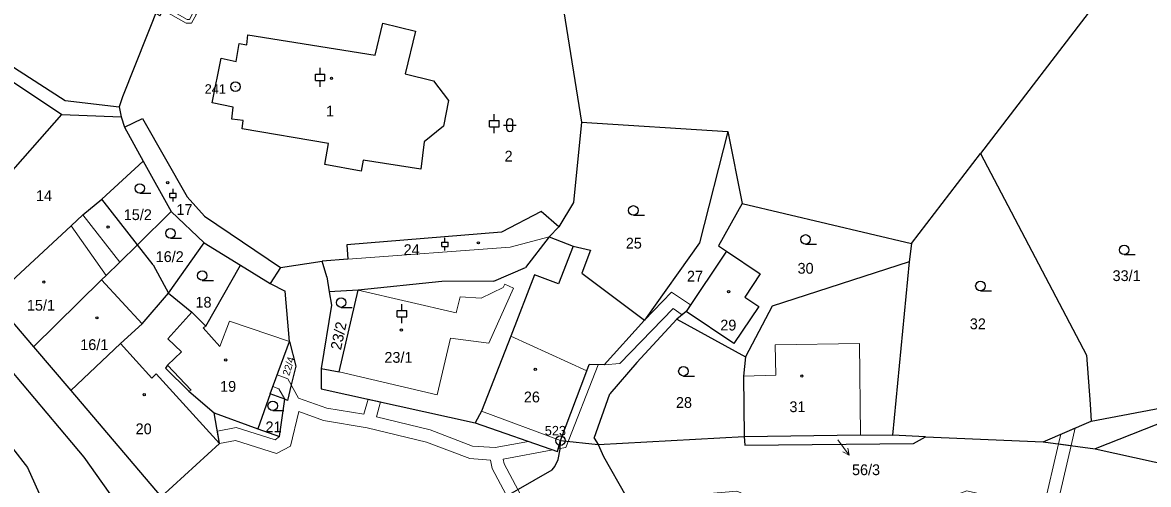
# Model space of a CAD drawing. Extents: x -727701 to -724405, y -960481 to -957284.
# Drawn here: x -726807.6 to -726630.1, y -958094.8 to -958022 of the extents above; entities that cross this region are included whole.
import ezdxf
from ezdxf.enums import TextEntityAlignment as Align

# ---------------------------------------------------------------- set-up
doc = ezdxf.new("R2010")
doc.units = 0
doc.header["$LTSCALE"] = 0.68
for name, color, linetype, lineweight in [('1', 7, 'Continuous', 25), ('13', 7, 'Continuous', 13), ('3', 7, 'Continuous', 25), ('4', 7, 'Continuous', 13), ('5', 7, 'Continuous', 25), ('7', 7, 'Continuous', 13), ('8', 7, 'Continuous', 25)]:
    doc.layers.add(name, color=color, linetype=linetype, lineweight=lineweight)
doc.layers.add('2', color=7, linetype='Continuous')

msp = doc.modelspace()

# ---------------------------------------------------------------- linework, layer by layer
at = {"layer": '1'}
for p, q in [((-726634.18, -958013.37), (-726656.63, -958042.62)), ((-726786, -958019), (-726791.84, -958033.67)), ((-726722.3, -958020.3), (-726719.49, -958037.65)), ((-726752.03, -958027.13), (-726750.81, -958022.07)), ((-726750.81, -958022.07), (-726745.67, -958023.32)), ((-726772.22, -958025.48), (-726772.11, -958023.89)), ((-726772.11, -958023.89), (-726752.03, -958027.13)), ((-726745.67, -958023.32), (-726747.3, -958030.05)), ((-726773.92, -958028.08), (-726773.45, -958025.28)), ((-726773.45, -958025.28), (-726772.22, -958025.48)), ((-726777.71, -958034.63), (-726776.28, -958027.6)), ((-726776.28, -958027.6), (-726773.92, -958028.08)), ((-726813.67, -958028.25), (-726801.41, -958036.44)), ((-726809.73, -958028.54), (-726800.87, -958034.27)), ((-726747.3, -958030.05), (-726742.82, -958031.14)), ((-726742.82, -958031.14), (-726740.46, -958034.25)), ((-726800.87, -958034.27), (-726792.34, -958035.24)), ((-726791.84, -958033.67), (-726792.34, -958035.24)), ((-726792.34, -958035.24), (-726792.05, -958036.83)), ((-726774.42, -958035.3), (-726777.71, -958034.63)), ((-726774.61, -958037.2), (-726774.42, -958035.3)), ((-726740.46, -958034.25), (-726741.23, -958038.3)), ((-726811, -958047.4), (-726801.41, -958036.44)), ((-726801.41, -958036.44), (-726792.05, -958036.83)), ((-726792.05, -958036.83), (-726791.53, -958038.45)), ((-726791.53, -958038.45), (-726788.71, -958037.06)), ((-726788.71, -958037.06), (-726781.66, -958049.45)), ((-726791.53, -958038.45), (-726788.56, -958043.82)), ((-726772.84, -958037.39), (-726774.61, -958037.2)), ((-726772.98, -958038.69), (-726772.84, -958037.39)), ((-726759.37, -958041.03), (-726772.98, -958038.69)), ((-726741.23, -958038.3), (-726744.3, -958040.75)), ((-726719.49, -958037.65), (-726720.78, -958050.32)), ((-726719.49, -958037.65), (-726696.44, -958039.15)), ((-726696.44, -958039.15), (-726700.89, -958056.67)), ((-726696.44, -958039.15), (-726694.19, -958050.5)), ((-726759.97, -958044.33), (-726759.37, -958041.03)), ((-726744.3, -958040.75), (-726744.8, -958045.05)), ((-726795.1, -958049.78), (-726788.56, -958043.82)), ((-726788.56, -958043.82), (-726784.19, -958051.72)), ((-726753.89, -958043.63), (-726754.21, -958045.38)), ((-726744.8, -958045.05), (-726753.89, -958043.63)), ((-726667.48, -958056.8), (-726656.63, -958042.62)), ((-726656.63, -958042.62), (-726639.88, -958074.4)), ((-726754.21, -958045.38), (-726759.97, -958044.33)), ((-726781.66, -958049.45), (-726778.93, -958052.5)), ((-726798.08, -958052.29), (-726795.1, -958049.78)), ((-726789.5, -958056.98), (-726795.1, -958049.78)), ((-726720.78, -958050.32), (-726723.08, -958054.16)), ((-726694.19, -958050.5), (-726697.9, -958057.17)), ((-726694.19, -958050.5), (-726667.48, -958056.8)), ((-726799.94, -958054), (-726798.08, -958052.29)), ((-726784.19, -958051.72), (-726778.95, -958056.7)), ((-726778.93, -958052.5), (-726766.93, -958060.55)), ((-726725.86, -958051.74), (-726732.1, -958055)), ((-726723.08, -958054.16), (-726725.86, -958051.74)), ((-726812.34, -958065.48), (-726799.94, -958054)), ((-726723.08, -958054.16), (-726724.57, -958055.73)), ((-726826.51, -958056.58), (-726797.94, -958090.46)), ((-726732.1, -958055), (-726756.5, -958057)), ((-726724.57, -958055.73), (-726728.3, -958060.55)), ((-726724.57, -958055.73), (-726720.82, -958057.18)), ((-726787.03, -958060.16), (-726789.5, -958056.98)), ((-726784.57, -958064.63), (-726778.95, -958056.7)), ((-726778.95, -958056.7), (-726773.25, -958060.2)), ((-726756.5, -958057), (-726756.3, -958059.27)), ((-726720.82, -958057.18), (-726723.14, -958063.16)), ((-726720.82, -958057.18), (-726718.08, -958057.84)), ((-726718.08, -958057.84), (-726719.46, -958061.48)), ((-726700.89, -958056.67), (-726709.57, -958068.85)), ((-726696.65, -958058), (-726703, -958067.5)), ((-726697.9, -958057.17), (-726696.65, -958058)), ((-726696.65, -958058), (-726691.31, -958061.57)), ((-726667.48, -958056.8), (-726667.86, -958059.69)), ((-726794.39, -958061.81), (-726792.27, -958059.72)), ((-726766.93, -958060.55), (-726760.36, -958059.59)), ((-726756.3, -958059.27), (-726760.36, -958059.59)), ((-726759.65, -958062.02), (-726760.36, -958059.59)), ((-726667.86, -958059.69), (-726689.43, -958066.67)), ((-726667.86, -958059.69), (-726670.46, -958087.01)), ((-726795.13, -958062.49), (-726794.39, -958061.81)), ((-726787.03, -958060.16), (-726784.57, -958064.63)), ((-726778.7, -958069.8), (-726773.25, -958060.2)), ((-726773.25, -958060.2), (-726768.55, -958063.1)), ((-726766.93, -958060.55), (-726768.55, -958063.1)), ((-726733.3, -958062.7), (-726728.3, -958060.55)), ((-726726.89, -958061.7), (-726730.65, -958071.41)), ((-726723.14, -958063.16), (-726726.89, -958061.7)), ((-726719.46, -958061.48), (-726709.57, -958068.85)), ((-726691.31, -958061.57), (-726693.76, -958065.26)), ((-726805.89, -958073.05), (-726795.13, -958062.49)), ((-726768.55, -958063.1), (-726766.22, -958064.32)), ((-726759.65, -958062.02), (-726759.24, -958064.42)), ((-726741.5, -958062.75), (-726754.68, -958064.12)), ((-726733.3, -958062.7), (-726741.5, -958062.75)), ((-726788.76, -958069.46), (-726784.57, -958064.63)), ((-726784.57, -958064.63), (-726780.9, -958067.59)), ((-726765.53, -958072.25), (-726766.22, -958064.32)), ((-726754.68, -958064.12), (-726759.24, -958064.42)), ((-726759.24, -958064.42), (-726758.89, -958066.48)), ((-726757.7, -958077.03), (-726754.68, -958064.12)), ((-726693.76, -958065.26), (-726691.57, -958066.7)), ((-726812.34, -958065.48), (-726805.89, -958073.05)), ((-726758.89, -958066.48), (-726760.54, -958076.51)), ((-726691.57, -958066.7), (-726695.47, -958072.54)), ((-726689.43, -958066.67), (-726693.66, -958074.62)), ((-726780.9, -958067.59), (-726784.71, -958071.83)), ((-726780.9, -958067.59), (-726778.7, -958069.8)), ((-726709.57, -958068.85), (-726715.94, -958075.93)), ((-726704.45, -958068.71), (-726710.79, -958075.52)), ((-726703, -958067.5), (-726704.45, -958068.71)), ((-726704.45, -958068.71), (-726693.66, -958074.62)), ((-726695.47, -958072.54), (-726703, -958067.5)), ((-726792.14, -958072.55), (-726788.76, -958069.46)), ((-726799.99, -958079.97), (-726792.14, -958072.55)), ((-726784.71, -958071.83), (-726782.55, -958073.85)), ((-726768.55, -958080.5), (-726765.53, -958072.25)), ((-726765.53, -958072.25), (-726764.5, -958076.13)), ((-726730.65, -958071.41), (-726735.23, -958083.21)), ((-726805.89, -958073.05), (-726799.99, -958079.97)), ((-726782.55, -958073.85), (-726784.75, -958075.94)), ((-726784.75, -958075.94), (-726785.05, -958076.45)), ((-726718.68, -958076.86), (-726718.3, -958075.85)), ((-726715.94, -958075.93), (-726718.3, -958075.85)), ((-726710.79, -958075.52), (-726715.02, -958080.5)), ((-726693.66, -958074.62), (-726693.94, -958077.71)), ((-726639.88, -958074.4), (-726639.34, -958082.13)), ((-726785.05, -958076.45), (-726781.41, -958080.08)), ((-726760.54, -958076.51), (-726760.53, -958079.68)), ((-726760.54, -958076.51), (-726757.7, -958077.03)), ((-726722.81, -958087.85), (-726718.68, -958076.86)), ((-726693.94, -958077.71), (-726693.86, -958087.19)), ((-726639.17, -958084.77), (-726610.68, -958079.34)), ((-726799.99, -958079.97), (-726785.73, -958096.72)), ((-726781.41, -958080.08), (-726777.38, -958083.49)), ((-726768.55, -958080.5), (-726770.5, -958086)), ((-726766.26, -958081.33), (-726768.55, -958080.5)), ((-726767.08, -958087.21), (-726766.26, -958081.33)), ((-726760.53, -958079.68), (-726736.26, -958085.03)), ((-726717.51, -958087.44), (-726715.02, -958080.5)), ((-726735.23, -958083.21), (-726736.26, -958085.03)), ((-726639.34, -958082.13), (-726639.17, -958084.77)), ((-726813.46, -958083.54), (-726806.79, -958092.11)), ((-726776.53, -958088.3), (-726777.38, -958083.49)), ((-726777.38, -958083.49), (-726770.5, -958086)), ((-726646.73, -958088.04), (-726639.17, -958084.77)), ((-726627.07, -958084.61), (-726638.52, -958089.14)), ((-726770.5, -958086), (-726767.08, -958087.21)), ((-726736.26, -958085.03), (-726723.27, -958089.58)), ((-726785.73, -958096.72), (-726776.53, -958088.3)), ((-726723.27, -958089.58), (-726722.81, -958087.85)), ((-726722.87, -958089.2), (-726722.81, -958087.85)), ((-726722.81, -958087.85), (-726716.86, -958088.47)), ((-726717.51, -958087.44), (-726716.86, -958088.47)), ((-726716.86, -958088.47), (-726693.86, -958087.19)), ((-726716.86, -958088.47), (-726716.02, -958090.34)), ((-726693.86, -958087.19), (-726675.5, -958086.94)), ((-726693.86, -958087.19), (-726693.74, -958088.58)), ((-726693.74, -958088.58), (-726667.19, -958088.31)), ((-726675.5, -958086.94), (-726670.46, -958087.01)), ((-726665.3, -958087.23), (-726670.46, -958087.01)), ((-726667.19, -958088.31), (-726665.3, -958087.23)), ((-726665.3, -958087.23), (-726646.73, -958088.04)), ((-726646.73, -958088.04), (-726638.52, -958089.14)), ((-726723.18, -958090.81), (-726722.87, -958089.2)), ((-726638.52, -958089.14), (-726614.35, -958094.5)), ((-726797.94, -958090.46), (-726791.6, -958099.4)), ((-726724.12, -958092.43), (-726723.68, -958091.94)), ((-726723.68, -958091.94), (-726723.18, -958090.81)), ((-726716.02, -958090.34), (-726712.52, -958096.53)), ((-726806.79, -958092.11), (-726802.49, -958101.65)), ((-726762.74, -958114.62), (-726724.12, -958092.43))]:
    msp.add_line(p, q, dxfattribs=at)
for points in [[(-726792.27, -958059.72), (-726789.5, -958056.98), (-726784.19, -958051.72)], [(-726764.5, -958076.13), (-726765.26, -958079.07), (-726765.82, -958081.51), (-726766.26, -958081.33)]]:
    msp.add_lwpolyline(points, dxfattribs=at)
at = {"layer": '13'}
for points in [[(-726785.68, -958019.12), (-726786.46, -958020.56), (-726785.95, -958020.93), (-726785.44, -958020.01), (-726781.83, -958022.08), (-726780.94, -958022.08), (-726780.17, -958020.62), (-726780.77, -958020.46), (-726781.3, -958021.48), (-726781.67, -958021.48), (-726785.15, -958019.49), (-726785.07, -958019.34)], [(-726705.3, -958064.45), (-726709.57, -958068.85), (-726715.94, -958075.93), (-726713.47, -958075.71), (-726705.03, -958067.04), (-726703.61, -958068.01), (-726703, -958067.5), (-726702.31, -958066.47)], [(-726718.3, -958075.85), (-726718.68, -958076.86), (-726722.81, -958087.85), (-726723.16, -958089.16), (-726721.98, -958088.95), (-726716.85, -958075.9)], [(-726643.94, -958086.83), (-726644.3, -958088.37), (-726642.31, -958088.63), (-726641.66, -958085.85)]]:
    msp.add_lwpolyline(points, close=True, dxfattribs=at)
for points in [[(-726725.49, -958103.19), (-726731.67, -958091.53), (-726731.84, -958090.75), (-726724.02, -958089.32), (-726727.83, -958087.98), (-726733.1, -958088.95), (-726736.65, -958088.72), (-726743.33, -958086.16), (-726751.82, -958084.1), (-726751.18, -958081.74), (-726753.13, -958081.31), (-726753.79, -958083.69), (-726759.64, -958082.72), (-726764.08, -958081.15), (-726765.78, -958078.1), (-726767.44, -958077.46), (-726768.13, -958079.34), (-726767.18, -958079.71), (-726766.26, -958081.33), (-726767.08, -958087.21), (-726767.76, -958087.72), (-726773.92, -958085.76), (-726776.88, -958086.34), (-726776.53, -958088.3), (-726774.03, -958087.82), (-726767.59, -958089.88), (-726765.38, -958088.75), (-726764.06, -958083.28), (-726760.14, -958084.66), (-726753.26, -958085.81), (-726743.92, -958088.07), (-726737.08, -958090.69), (-726733.86, -958090.91), (-726733.57, -958092.23), (-726727.05, -958104.51)], [(-726604.4, -958109.65), (-726644.73, -958099.04), (-726642.31, -958088.63), (-726644.3, -958088.37), (-726646.67, -958098.54), (-726658.74, -958095.77), (-726661.5, -958096.77), (-726693.5, -958096.46), (-726694.99, -958095.83), (-726709.76, -958097.1), (-726711.37, -958097.43), (-726710.03, -958098.34), (-726693, -958097.2), (-726661.42, -958098.23), (-726660, -958098.35), (-726658.6, -958097.84), (-726652.45, -958099.16), (-726652.59, -958099.8), (-726650.64, -958100.26), (-726650.5, -958099.62), (-726633.4, -958104.3), (-726628.95, -958105.15)]]:
    msp.add_lwpolyline(points, dxfattribs=at)
at = {"layer": '3'}
for p, q in [((-726760.68, -958030.091), (-726760.68, -958029.09)), ((-726761.431, -958030.091), (-726759.929, -958030.091)), ((-726761.431, -958031.092), (-726761.431, -958030.091)), ((-726761.431, -958031.092), (-726759.929, -958031.092)), ((-726760.68, -958032.09), (-726760.68, -958031.092)), ((-726759.929, -958031.092), (-726759.929, -958030.091)), ((-726733.24, -958037.421), (-726733.24, -958036.42)), ((-726733.991, -958037.421), (-726732.489, -958037.421)), ((-726733.991, -958038.422), (-726733.991, -958037.421)), ((-726733.991, -958038.422), (-726732.489, -958038.422)), ((-726733.24, -958039.42), (-726733.24, -958038.422)), ((-726732.489, -958038.422), (-726732.489, -958037.421)), ((-726731.801, -958038.131), (-726729.799, -958038.131)), ((-726731.301, -958037.631), (-726731.301, -958038.632)), ((-726730.299, -958038.632), (-726730.299, -958037.631)), ((-726789.113, -958048.86), (-726787.363, -958048.86)), ((-726784.383, -958048.851), (-726783.377, -958048.851)), ((-726784.383, -958049.522), (-726784.383, -958048.851)), ((-726783.88, -958048.851), (-726783.88, -958048.18)), ((-726783.377, -958049.522), (-726783.377, -958048.851)), ((-726784.383, -958049.522), (-726783.377, -958049.522)), ((-726783.88, -958050.19), (-726783.88, -958049.522)), ((-726711.323, -958052.32), (-726709.573, -958052.32)), ((-726784.283, -958055.93), (-726782.533, -958055.93)), ((-726741.513, -958056.561), (-726740.507, -958056.561)), ((-726741.513, -958057.232), (-726741.513, -958056.561)), ((-726741.01, -958056.561), (-726741.01, -958055.89)), ((-726740.507, -958057.232), (-726740.507, -958056.561)), ((-726741.513, -958057.232), (-726740.507, -958057.232)), ((-726741.01, -958057.9), (-726741.01, -958057.232)), ((-726684.183, -958056.89), (-726682.433, -958056.89)), ((-726633.963, -958058.54), (-726632.213, -958058.54)), ((-726779.273, -958062.59), (-726777.523, -958062.59)), ((-726656.623, -958064.23), (-726654.873, -958064.23)), ((-726757.383, -958066.85), (-726755.633, -958066.85)), ((-726747.8, -958067.341), (-726747.8, -958066.34)), ((-726748.551, -958067.341), (-726747.049, -958067.341)), ((-726748.551, -958068.342), (-726748.551, -958067.341)), ((-726748.551, -958068.342), (-726747.049, -958068.342)), ((-726747.8, -958069.34), (-726747.8, -958068.342)), ((-726747.049, -958068.342), (-726747.049, -958067.341)), ((-726703.433, -958077.67), (-726701.683, -958077.67)), ((-726768.163, -958083.12), (-726766.413, -958083.12))]:
    msp.add_line(p, q, dxfattribs=at)
for centre in [(-726789.1129, -958048.1098), (-726711.3229, -958051.5698), (-726784.2829, -958055.1798), (-726684.1829, -958056.1398), (-726633.9629, -958057.7898), (-726779.2729, -958061.8398), (-726656.6229, -958063.4798), (-726757.3829, -958066.0998), (-726703.4329, -958076.9198), (-726768.1629, -958082.3698)]:
    msp.add_circle(centre, 0.75, dxfattribs=at)
for centre, start, end in [((-726730.8, -958037.6309), 0, 180), ((-726730.8, -958038.6309), 180, 359.98789)]:
    msp.add_arc(centre, 0.5, start, end, dxfattribs=at)
at = {"layer": '4'}
for p, q in [((-726798.08, -958052.29), (-726792.27, -958059.72)), ((-726799.94, -958054), (-726794.39, -958061.81)), ((-726730.74, -958057.37), (-726724.57, -958055.73)), ((-726756.3, -958059.27), (-726730.74, -958057.37)), ((-726795.13, -958062.49), (-726788.76, -958069.46)), ((-726731.83, -958063.73), (-726731.58, -958063.18)), ((-726731.58, -958063.18), (-726730.19, -958063.81)), ((-726754.68, -958064.12), (-726739.23, -958067.73)), ((-726739.23, -958067.73), (-726738.64, -958065.19)), ((-726738.64, -958065.19), (-726735.29, -958065.41)), ((-726735.29, -958065.41), (-726731.83, -958063.73)), ((-726730.19, -958063.81), (-726734.12, -958072.47)), ((-726776.5, -958073), (-726775, -958069)), ((-726775, -958069), (-726765.53, -958072.25)), ((-726778.7, -958069.8), (-726779.1, -958070.05)), ((-726779.1, -958070.05), (-726776.5, -958073)), ((-726792.14, -958072.55), (-726787.22, -958077.99)), ((-726740.16, -958071.72), (-726742.25, -958080.65)), ((-726734.12, -958072.47), (-726740.16, -958071.72)), ((-726730.65, -958071.41), (-726718.68, -958076.86)), ((-726688.96, -958072.74), (-726675.7, -958072.56)), ((-726675.7, -958072.56), (-726675.5, -958086.94)), ((-726688.89, -958077.55), (-726688.96, -958072.74)), ((-726781, -958079.9), (-726784.75, -958075.94)), ((-726787.22, -958077.99), (-726786.55, -958077.32)), ((-726786.55, -958077.32), (-726776.53, -958088.3)), ((-726742.25, -958080.65), (-726757.7, -958077.03)), ((-726693.94, -958077.71), (-726688.89, -958077.55)), ((-726781.41, -958080.08), (-726781, -958079.9)), ((-726722.81, -958087.85), (-726735.23, -958083.21))]:
    msp.add_line(p, q, dxfattribs=at)
at = {"layer": '5'}
for centre in [(-726758.8968, -958030.7592), (-726784.7068, -958047.2092), (-726794.1068, -958054.1992), (-726735.7468, -958056.6792), (-726804.2368, -958062.8592), (-726696.3068, -958064.3692), (-726795.8768, -958068.4992), (-726747.8868, -958070.4292), (-726775.5668, -958075.1292), (-726726.7868, -958076.6092), (-726684.7668, -958077.6692), (-726788.4168, -958080.5992)]:
    msp.add_circle(centre, 0.175, dxfattribs=at)
at = {"layer": '7'}
msp.add_line((-726677.304, -958090.127), (-726677.507, -958089.026), dxfattribs=at)
msp.add_lwpolyline([(-726679.11, -958087.73), (-726677.304, -958090.127), (-726678.307, -958089.628)], dxfattribs=at)
at = {"layer": '8'}
for centre, radius in [((-726774.04, -958032.0698), 0.75), ((-726774.04, -958032.0698), 0.03), ((-726722.81, -958087.8498), 0.75), ((-726722.81, -958087.8498), 0.03)]:
    msp.add_circle(centre, radius, dxfattribs=at)

# ---------------------------------------------------------------- texts
at = {"layer": '2'}
for s, p in [('1', (-726759.76, -958036.765)), ('2', (-726731.62, -958043.865)), ('17', (-726783.34, -958052.285)), ('15/2', (-726791.64, -958053.095)), ('25', (-726712.51, -958057.585)), ('16/2', (-726786.61, -958059.705)), ('24', (-726747.53, -958058.605)), ('30', (-726685.44, -958061.545)), ('27', (-726702.87, -958062.785)), ('18', (-726780.34, -958066.895)), ('15/1', (-726806.91, -958067.365)), ('29', (-726697.62, -958070.495)), ('32', (-726658.29, -958070.295)), ('16/1', (-726798.5, -958073.575)), ('23/1', (-726750.56, -958075.585)), ('19', (-726776.46, -958080.155)), ('26', (-726728.58, -958081.825)), ('28', (-726704.61, -958082.695)), ('31', (-726686.72, -958083.365)), ('21', (-726769.3, -958086.535)), ('20', (-726789.77, -958086.845)), ('56/3', (-726676.86, -958093.295))]:
    msp.add_text(s, height=1.7, dxfattribs=at).set_placement(p)
for s, p in [('14', (-726804.209, -958050.095)), ('33/1', (-726633.579, -958062.705))]:
    msp.add_text(s, height=1.7, dxfattribs=at).set_placement(p, align=Align.CENTER)
msp.add_text('23/2', height=1.7, rotation=78, dxfattribs=at).set_placement((-726757.414, -958073.668))
msp.add_text('22/4', height=1.139, rotation=73, dxfattribs=at).set_placement((-726765.1209, -958076.2875), align=Align.CENTER)
at = {"layer": '8'}
msp.add_text('241', height=1.5, dxfattribs=at).set_placement((-726775.539, -958033.187), align=Align.RIGHT)
msp.add_text('523', height=1.5, dxfattribs=at).set_placement((-726725.28, -958087.035))

doc.saveas('drawing.dxf')
